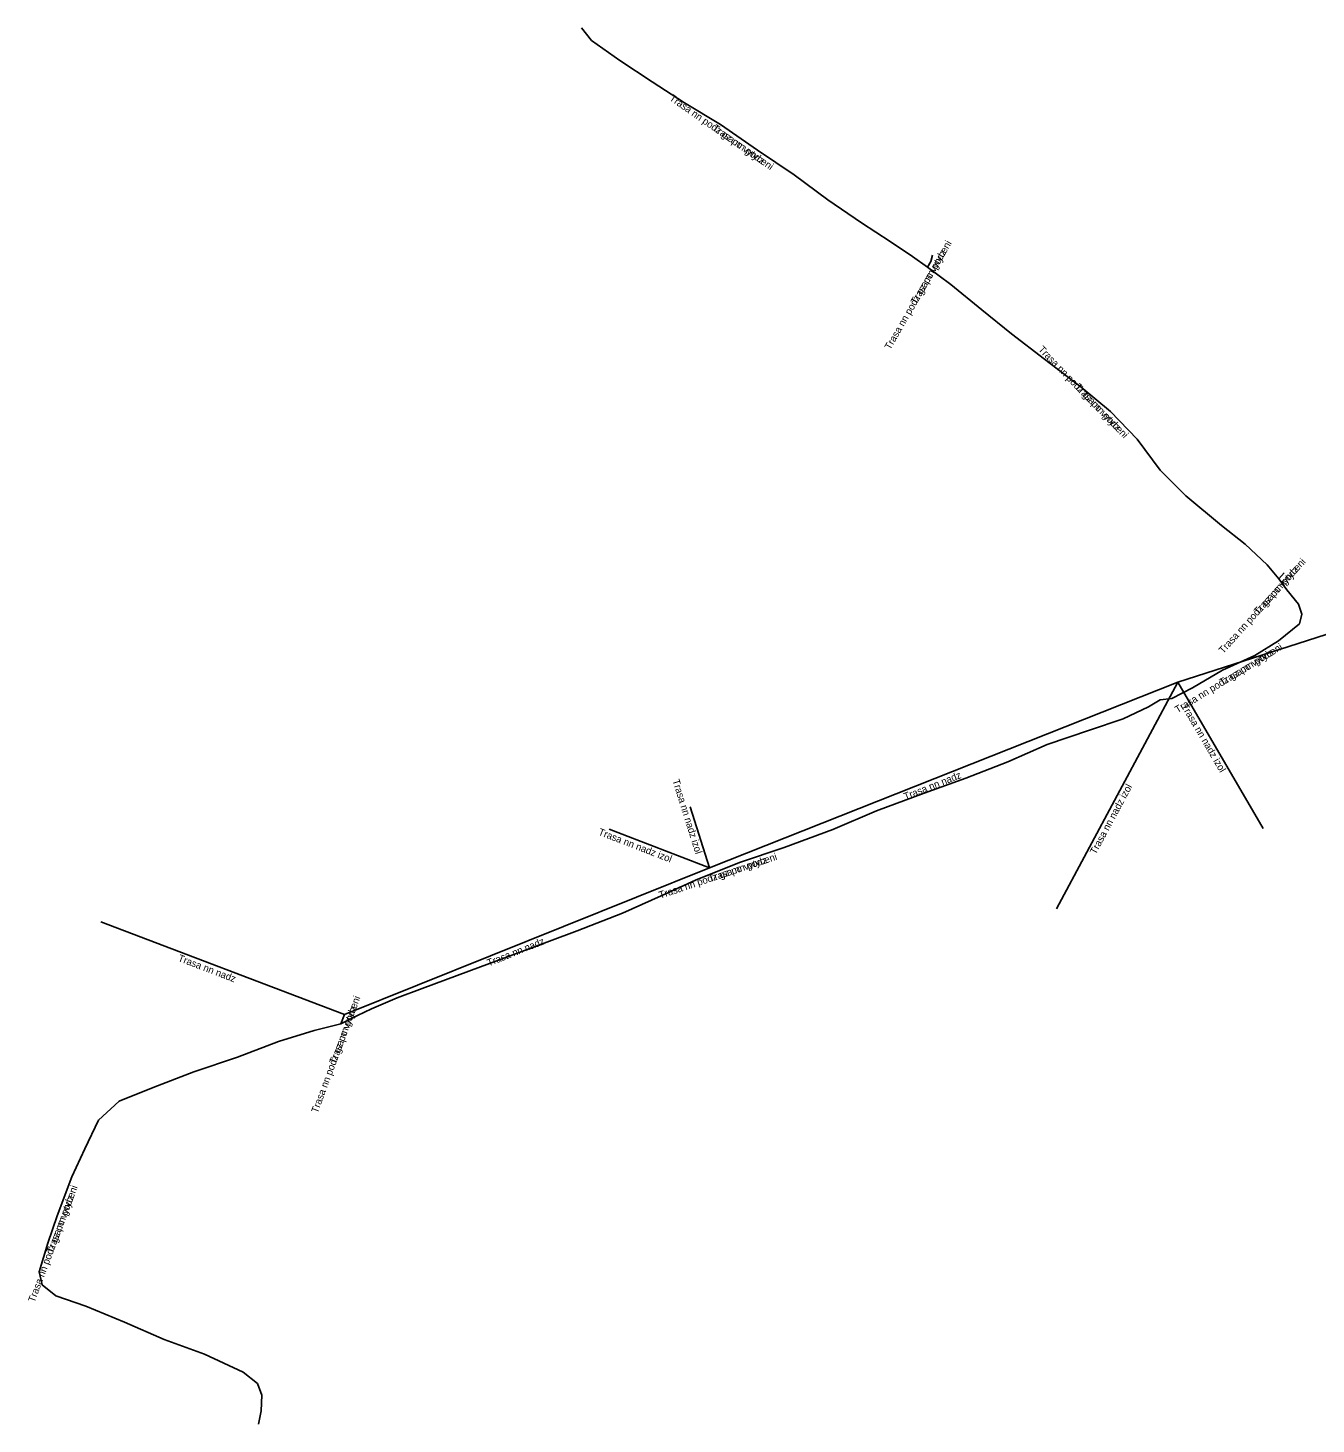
# Model space of a CAD drawing. Extents: x -866245 to -865998, y -1039827 to -1039605.
# Drawn here: x -866200.1 to -866109.6, y -1039815 to -1039716.9 of the extents above; entities that cross this region are included whole.
import ezdxf

# ---------------------------------------------------------------- set-up
doc = ezdxf.new("R2010")
doc.units = 0
doc.layers.add('Popiskový text - Ostatní atributy Trasy', color=7, linetype='Continuous')
doc.layers.add('Spojnice NN', color=7, linetype='Continuous')

msp = doc.modelspace()

# ---------------------------------------------------------------- linework, layer by layer
at = {"layer": 'Spojnice NN'}
for points in [[(-866136.92, -1039733.74), (-866137.97, -1039733), (-866139.55, -1039731.95), (-866141.56, -1039730.63), (-866143.91, -1039729.01), (-866146.28, -1039727.25), (-866148.86, -1039725.53), (-866151.46, -1039723.72), (-866153.98, -1039722.2), (-866156.25, -1039720.73), (-866158.52, -1039719.22), (-866160.51, -1039717.83), (-866161.23, -1039716.94)], [(-866136.92, -1039733.74), (-866137.97, -1039733), (-866139.55, -1039731.95), (-866141.56, -1039730.63), (-866143.91, -1039729.01), (-866146.28, -1039727.25), (-866148.86, -1039725.53), (-866151.46, -1039723.72), (-866153.98, -1039722.2), (-866156.25, -1039720.73), (-866158.52, -1039719.22), (-866160.51, -1039717.83), (-866161.23, -1039716.94)], [(-866136.92, -1039733.74), (-866136.69, -1039733.34), (-866136.56, -1039732.9)], [(-866136.92, -1039733.74), (-866136.69, -1039733.34), (-866136.56, -1039732.9)], [(-866112.23, -1039755.63), (-866113.06, -1039754.66), (-866114.6, -1039753.21), (-866116.27, -1039751.89), (-866118.78, -1039749.82), (-866120.57, -1039748), (-866122.18, -1039745.84), (-866124.07, -1039743.89), (-866126.13, -1039742.17), (-866128.69, -1039740.2), (-866131.01, -1039738.43), (-866133.1, -1039736.75), (-866135.28, -1039734.96), (-866136.92, -1039733.74)], [(-866112.23, -1039755.63), (-866113.06, -1039754.66), (-866114.6, -1039753.21), (-866116.27, -1039751.89), (-866118.78, -1039749.82), (-866120.57, -1039748), (-866122.18, -1039745.84), (-866124.07, -1039743.89), (-866126.13, -1039742.17), (-866128.69, -1039740.2), (-866131.01, -1039738.43), (-866133.1, -1039736.75), (-866135.28, -1039734.96), (-866136.92, -1039733.74)], [(-866092.586, -1039754.305), (-866119.332, -1039762.901)], [(-866120.57, -1039764.14), (-866119.76, -1039764.04), (-866118.3, -1039763.31), (-866116.19, -1039762.06), (-866113.93, -1039761.02), (-866112.26, -1039760), (-866110.78, -1039758.8), (-866110.61, -1039758.13), (-866110.86, -1039757.43), (-866111.67, -1039756.42), (-866112.23, -1039755.63)], [(-866120.57, -1039764.14), (-866119.76, -1039764.04), (-866118.3, -1039763.31), (-866116.19, -1039762.06), (-866113.93, -1039761.02), (-866112.26, -1039760), (-866110.78, -1039758.8), (-866110.61, -1039758.13), (-866110.86, -1039757.43), (-866111.67, -1039756.42), (-866112.23, -1039755.63)], [(-866112.23, -1039755.63), (-866111.86, -1039755.22)], [(-866112.23, -1039755.63), (-866111.86, -1039755.22)], [(-866119.332, -1039762.901), (-866152.234, -1039775.949)], [(-866119.332, -1039762.901), (-866127.865, -1039778.833)], [(-866119.332, -1039762.901), (-866113.335, -1039773.178)], [(-866120.57, -1039764.14), (-866121.4, -1039764.64), (-866123.17, -1039765.47), (-866125.53, -1039766.27), (-866128.5, -1039767.29), (-866131.27, -1039768.49), (-866134.22, -1039769.64), (-866137.14, -1039770.7), (-866140.49, -1039771.94), (-866143.56, -1039773.25), (-866146.99, -1039774.52), (-866150.13, -1039775.57), (-866153.22, -1039776.8), (-866155.63, -1039777.92), (-866158.34, -1039779.14), (-866161.53, -1039780.36), (-866165.42, -1039781.82), (-866169.13, -1039783.21), (-866172.41, -1039784.41), (-866174.18, -1039785.07), (-866175.98, -1039785.85), (-866176.95, -1039786.32), (-866178.12, -1039786.9)], [(-866120.57, -1039764.14), (-866121.4, -1039764.64), (-866123.17, -1039765.47), (-866125.53, -1039766.27), (-866128.5, -1039767.29), (-866131.27, -1039768.49), (-866134.22, -1039769.64), (-866137.14, -1039770.7), (-866140.49, -1039771.94), (-866143.56, -1039773.25), (-866146.99, -1039774.52), (-866150.13, -1039775.57), (-866153.22, -1039776.8), (-866155.63, -1039777.92), (-866158.34, -1039779.14), (-866161.53, -1039780.36), (-866165.42, -1039781.82), (-866169.13, -1039783.21), (-866172.41, -1039784.41), (-866174.18, -1039785.07), (-866175.98, -1039785.85), (-866176.95, -1039786.32), (-866178.12, -1039786.9)], [(-866152.234, -1039775.949), (-866153.578, -1039771.652)], [(-866152.234, -1039775.949), (-866159.275, -1039773.229)], [(-866152.234, -1039775.949), (-866177.88, -1039786.25)], [(-866177.88, -1039786.25), (-866194.992, -1039779.73)], [(-866178.12, -1039786.9), (-866177.88, -1039786.25)], [(-866178.12, -1039786.9), (-866177.88, -1039786.25)], [(-866183.91, -1039815.02), (-866183.73, -1039814.09), (-866183.68, -1039812.99), (-866183.99, -1039812.18), (-866184.98, -1039811.37), (-866187.71, -1039810.12), (-866190.54, -1039809.08), (-866193.32, -1039807.87), (-866196.03, -1039806.73), (-866198.16, -1039806), (-866199.1, -1039805.24), (-866199.33, -1039804.32), (-866198.71, -1039802.3), (-866198.06, -1039800.4), (-866197.03, -1039797.64), (-866196.12, -1039795.68), (-866195.14, -1039793.67), (-866193.71, -1039792.34), (-866191.32, -1039791.37), (-866188.45, -1039790.27), (-866185.38, -1039789.25), (-866182.51, -1039788.15), (-866179.99, -1039787.36), (-866178.12, -1039786.9)], [(-866183.91, -1039815.02), (-866183.73, -1039814.09), (-866183.68, -1039812.99), (-866183.99, -1039812.18), (-866184.98, -1039811.37), (-866187.71, -1039810.12), (-866190.54, -1039809.08), (-866193.32, -1039807.87), (-866196.03, -1039806.73), (-866198.16, -1039806), (-866199.1, -1039805.24), (-866199.33, -1039804.32), (-866198.71, -1039802.3), (-866198.06, -1039800.4), (-866197.03, -1039797.64), (-866196.12, -1039795.68), (-866195.14, -1039793.67), (-866193.71, -1039792.34), (-866191.32, -1039791.37), (-866188.45, -1039790.27), (-866185.38, -1039789.25), (-866182.51, -1039788.15), (-866179.99, -1039787.36), (-866178.12, -1039786.9)]]:
    msp.add_lwpolyline(points, dxfattribs=at)

# ---------------------------------------------------------------- texts
at = {"layer": 'Popiskový text - Ostatní atributy Trasy'}
for s, rotation, p in [('Trasa nn podz gz po vytyceni', 325.15615, (-866155.093, -1039721.982)), ('Trasa nn podz', 325.15615, (-866152.069, -1039724.088)), ('Trasa nn podz gz po vytyceni', 60.1011, (-866139.533, -1039739.589)), ('Trasa nn podz', 60.1011, (-866137.696, -1039736.394)), ('Trasa nn podz gz po vytyceni', 314.10483, (-866129.168, -1039739.565)), ('Trasa nn podz', 314.10483, (-866126.603, -1039742.211)), ('Trasa nn podz gz po vytyceni', 47.93567, (-866116.14, -1039760.933)), ('Trasa nn podz', 47.93567, (-866113.671, -1039758.197)), ('Trasa nn podz gz po vytyceni', 31.41569, (-866119.35, -1039765.092)), ('Trasa nn podz', 31.41569, (-866116.205, -1039763.171)), ('Trasa nn nadz izol', 300.26467, (-866119.107, -1039764.576)), ('Trasa nn nadz', 21.6315, (-866138.47, -1039771.19)), ('Trasa nn nadz izol', 287.37262, (-866154.837, -1039769.805)), ('Trasa nn nadz izol', 61.82485, (-866125.098, -1039775.044)), ('Trasa nn nadz izol', 338.87584, (-866160.084, -1039773.613)), ('Trasa nn podz gz po vytyceni', 18.48967, (-866155.687, -1039778.114)), ('Trasa nn podz', 18.48967, (-866152.192, -1039776.945)), ('Trasa nn nadz', 21.88341, (-866167.736, -1039782.876)), ('Trasa nn nadz', 339.14203, (-866189.609, -1039782.477)), ('Trasa nn podz gz po vytyceni', 69.7343, (-866179.757, -1039793.21)), ('Trasa nn podz', 69.7343, (-866178.481, -1039789.753)), ('Trasa nn podz gz po vytyceni', 69.53501, (-866199.646, -1039806.509)), ('Trasa nn podz', 69.53501, (-866198.357, -1039803.056))]:
    msp.add_text(s, height=0.5, rotation=rotation, dxfattribs=at).set_placement(p)

doc.saveas('drawing.dxf')
